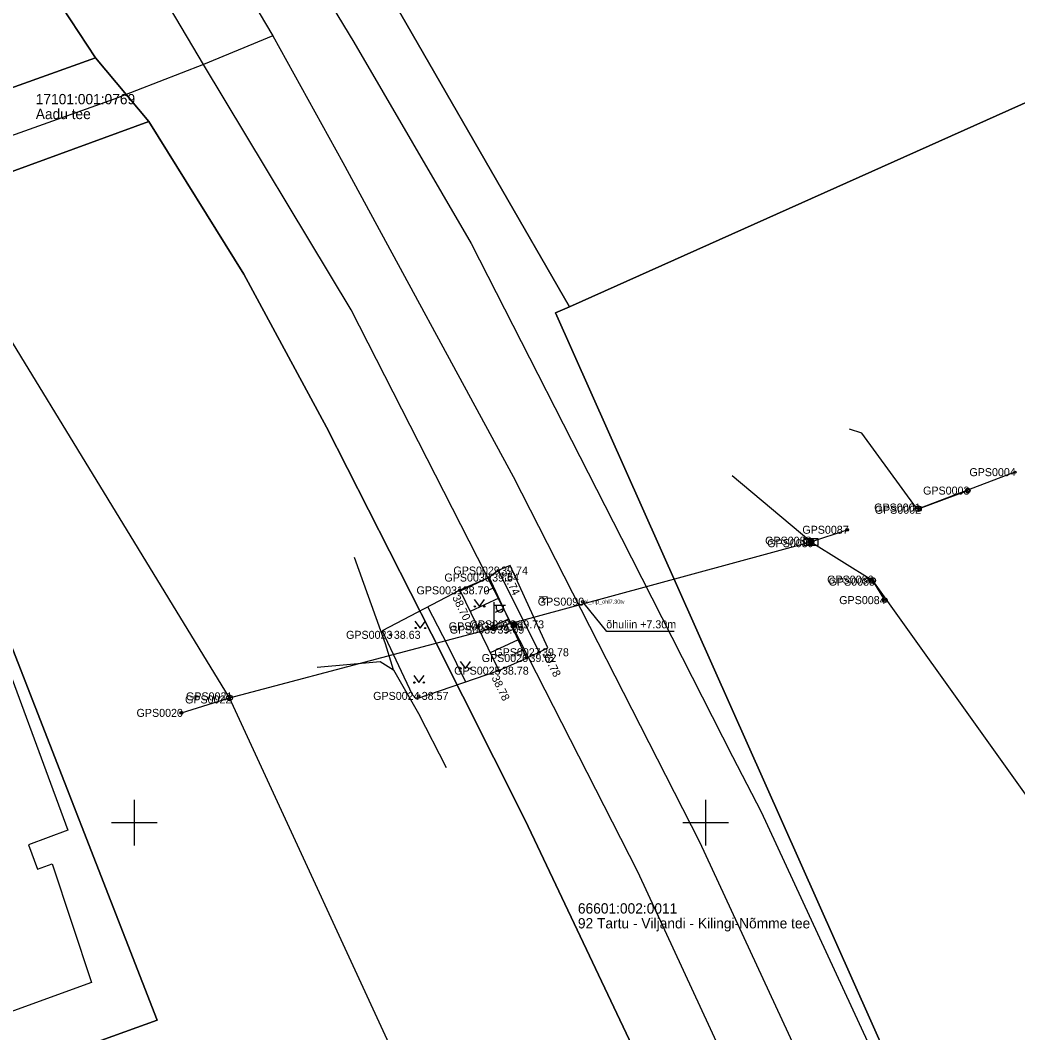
# Model space of a CAD drawing. Extents: x 626224 to 628280, y 6467750 to 6471135.
# Drawn here: x 627790 to 627877.3, y 6468381.6 to 6468470.2 of the extents above; entities that cross this region are included whole.
import ezdxf

# ---------------------------------------------------------------- set-up
doc = ezdxf.new("R2010")
doc.units = 0
for name, color, linetype in [('ELRAJATISMP', 7, 'Continuous'), ('HALJASTUS', 7, 'Continuous'), ('Hoone Elu- või ühiskondlik hoone', 7, 'Continuous'), ('KORGUS-EH2000', 7, 'Continuous'), ('KPKAABEL', 7, 'Continuous'), ('KPOHULIIN', 7, 'Continuous'), ('MAAMUDEL', 7, 'Continuous'), ('MOOTKORG-EH2000', 7, 'Continuous'), ('MOOTMPUNKT', 7, 'Continuous'), ('MOOTNR', 7, 'Continuous'), ('MOOTPIIR', 7, 'Continuous'), ('MPKAABEL', 7, 'Continuous'), ('MPOHULIIN', 7, 'Continuous'), ('PIIR', 7, 'Continuous'), ('POST', 7, 'Continuous'), ('RELJEEF', 7, 'Continuous'), ('SITRASS', 7, 'Continuous'), ('TEE', 7, 'Continuous'), ('Tee Liiklusala', 7, 'Continuous'), ('Tee Muu tee Püsikate', 7, 'Continuous'), ('Tee Põhimaantee Püsikate', 7, 'Continuous'), ('VORK', 7, 'Continuous')]:
    doc.layers.add(name, color=color, linetype=linetype)

msp = doc.modelspace()

# ---------------------------------------------------------------- linework, layer by layer
at = {"layer": 'ELRAJATISMP'}
for p, q in [((627859.089, 6468424.856), (627859.089, 6468424.259)), ((627859.36, 6468424.856), (627859.36, 6468424.259))]:
    msp.add_line(p, q, dxfattribs=at)
msp.add_lwpolyline([(627858.627, 6468424.856), (627859.822, 6468424.856), (627859.822, 6468424.259), (627858.627, 6468424.259)], close=True, dxfattribs=at)
at = {"layer": 'HALJASTUS'}
for p, q in [((627829.743, 6468419.52), (627830.207, 6468418.913)), ((627830.207, 6468418.913), (627830.652, 6468419.52)), ((627824.568, 6468417.633), (627825.031, 6468417.026)), ((627825.031, 6468417.026), (627825.477, 6468417.633)), ((627828.512, 6468414.09), (627828.975, 6468413.484)), ((627828.975, 6468413.484), (627829.421, 6468414.09)), ((627824.453, 6468412.858), (627824.916, 6468412.251)), ((627824.916, 6468412.251), (627825.362, 6468412.858))]:
    msp.add_line(p, q, dxfattribs=at)
for centre in [(627829.806, 6468418.913), (627830.634, 6468418.913), (627824.63, 6468417.026), (627825.459, 6468417.026), (627828.574, 6468413.484), (627829.403, 6468413.484), (627824.515, 6468412.251), (627825.344, 6468412.251)]:
    msp.add_circle(centre, 0.055, dxfattribs=at)
at = {"layer": 'Hoone Elu- või ühiskondlik hoone'}
msp.add_lwpolyline([(627782.134, 6468418.559), (627783.024, 6468416.148), (627787.374, 6468417.759), (627794.183, 6468399.339), (627790.744, 6468398.069), (627791.544, 6468395.918), (627792.806, 6468396.379), (627796.243, 6468386.017), (627788.121, 6468383.056), (627784.754, 6468393.178), (627785.402, 6468393.411), (627776.874, 6468416.554), (627776.074, 6468416.259), (627772.824, 6468425.129), (627780.904, 6468428.069), (627784.124, 6468419.309)], close=True, dxfattribs=at)
at = {"layer": 'KORGUS-EH2000'}
for centre in [(627831.853, 6468422.053), (627828.482, 6468420.323), (627822.455, 6468416.43), (627835.432, 6468414.905), (627831.919, 6468413.296), (627824.898, 6468411.085)]:
    msp.add_circle(centre, 0.1, dxfattribs=at)
at = {"layer": 'KPKAABEL'}
msp.add_lwpolyline([(627868.629, 6468427.468), (627868.453, 6468427.501), (627863.683, 6468434.084), (627862.597, 6468434.434)], dxfattribs=at)
at = {"layer": 'KPOHULIIN'}
msp.add_line((627877.08, 6468430.663), (627868.629, 6468427.468), dxfattribs=at)
at = {"layer": 'MOOTMPUNKT'}
for centre in [(627877.08, 6468430.663), (627872.956, 6468429.05), (627868.535, 6468427.565), (627868.723, 6468427.371), (627862.388, 6468425.622), (627859.134, 6468424.667), (627859.315, 6468424.448), (627831.853, 6468422.053), (627831.061, 6468421.44), (627864.562, 6468421.262), (627864.688, 6468421.082), (627828.482, 6468420.323), (627839.234, 6468419.334), (627865.687, 6468419.466), (627831.441, 6468417.175), (627833.263, 6468417.344), (627822.455, 6468416.43), (627831.527, 6468416.886), (627835.432, 6468414.905), (627834.326, 6468414.401), (627831.919, 6468413.296), (627808.306, 6468411.047), (627824.898, 6468411.085), (627808.362, 6468410.774), (627804.121, 6468409.6)]:
    msp.add_circle(centre, 0.1, dxfattribs=at)
at = {"layer": 'MOOTPIIR'}
msp.add_lwpolyline([(627824.32, 6468411.202), (627824.662, 6468410.817), (627831.919, 6468413.296), (627834.326, 6468414.401), (627835.432, 6468414.905), (627836.182, 6468415.277), (627832.898, 6468422.5), (627831.853, 6468422.053), (627831.061, 6468421.44), (627828.482, 6468420.323), (627821.691, 6468416.785)], close=True, dxfattribs=at)
at = {"layer": 'MPKAABEL'}
msp.add_line((627859.225, 6468424.557), (627852.332, 6468430.34), dxfattribs=at)
msp.add_lwpolyline([(627847.256, 6468416.733), (627841.35, 6468416.714), (627839.374, 6468419.171)], dxfattribs=at)
at = {"layer": 'MPOHULIIN'}
for points in [[(627835.693, 6468351.671), (627824.767, 6468375.343), (627808.334, 6468410.91), (627776.772, 6468462.547)], [(627834.957, 6468417.972), (627859.225, 6468424.557), (627864.625, 6468421.172)], [(627987.699, 6468154.836), (627974.224, 6468199.228), (627965.015, 6468229.514), (627942.938, 6468278.292), (627925.229, 6468317.293), (627901.803, 6468369.191), (627885.677, 6468391.746), (627864.625, 6468421.172)], [(627822.673, 6468414.701), (627831.484, 6468417.03), (627834.957, 6468417.972)], [(627808.334, 6468410.91), (627822.673, 6468414.701)]]:
    msp.add_lwpolyline(points, dxfattribs=at)
at = {"layer": 'PIIR'}
for points in [[(627932.6, 6468557.07), (627965.68, 6468502.25), (627838.09, 6468445.14), (627818.92, 6468478.42), (627816.33, 6468482.77), (627807.45, 6468497.75)], [(627796.62, 6468466.91), (627730.26, 6468443.18), (627664.7, 6468422.83), (627644.76, 6468421.52), (627633.52, 6468445.58), (627608.44, 6468499.25), (627666.94, 6468517.08), (627746.91, 6468541.23), (627793.54, 6468471.56), (627793.68, 6468471.35)], [(627965.68, 6468502.25), (628025.29, 6468403.44), (627924.44, 6468351.42), (627930.15, 6468335.32), (627893.5, 6468317.49), (627836.88, 6468444.6), (627838.09, 6468445.14)], [(627664.45, 6468365.98), (627644.76, 6468421.52), (627664.7, 6468422.83), (627730.26, 6468443.18), (627796.62, 6468466.91), (627801.28, 6468461.34), (627775.07, 6468451.79), (627729.69, 6468435.15), (627697.47, 6468426.57), (627658.9, 6468411.81), (627655.45, 6468401.9), (627668.1, 6468374.6), (627685.55, 6468339.27), (627702.17, 6468303.93), (627693.67, 6468299.87)], [(627802, 6468382.71), (627775.07, 6468451.79), (627801.28, 6468461.34), (627809.58, 6468448), (627816.81, 6468434.6), (627826.02, 6468416.53), (627834.21, 6468400.21), (627843.3, 6468381.02), (627850.92, 6468363.47), (627860.61, 6468341.12), (627869.05, 6468319.44), (627817.44, 6468300.95), (627762.12, 6468283.97), (627745.3, 6468323.41), (627778.35, 6468337.62), (627766.32, 6468369.86)], [(627775.07, 6468451.79), (627802, 6468382.71), (627766.32, 6468369.86), (627762.49, 6468377.13), (627743.21, 6468369.09), (627733.67, 6468392.46), (627728.72, 6468407.08), (627739.62, 6468413.09), (627729.69, 6468435.15)]]:
    msp.add_lwpolyline(points, close=True, dxfattribs=at)
msp.add_lwpolyline([(627869.05, 6468319.44), (627860.61, 6468341.12), (627850.92, 6468363.47), (627843.3, 6468381.02), (627834.21, 6468400.21), (627826.02, 6468416.53), (627816.81, 6468434.6), (627809.58, 6468448), (627801.28, 6468461.34), (627796.62, 6468466.91), (627793.68, 6468471.35), (627793.54, 6468471.56), (627816.33, 6468482.77), (627818.92, 6468478.42), (627838.09, 6468445.14), (627836.88, 6468444.6), (627893.5, 6468317.49)], dxfattribs=at)
at = {"layer": 'POST'}
for p, q in [((627831.484, 6468417.28), (627831.484, 6468419.28)), ((627831.484, 6468419.03), (627832.484, 6468419.03)), ((627831.711, 6468418.709), (627831.711, 6468419.03)), ((627832.324, 6468418.709), (627832.324, 6468419.03)), ((627833.085, 6468417.168), (627833.439, 6468417.521)), ((627831.484, 6468417.03), (627831.484, 6468417.03))]:
    msp.add_line(p, q, dxfattribs=at)
for points in [[(627868.629, 6468427.468), (627872.956, 6468429.05)], [(627859.225, 6468424.557), (627862.388, 6468425.622)], [(627865.687, 6468419.466), (627864.625, 6468421.172)], [(627804.121, 6468409.6), (627808.334, 6468410.91)]]:
    msp.add_lwpolyline(points, dxfattribs=at)
for centre, radius in [((627872.956, 6468429.05), 0.2), ((627868.629, 6468427.468), 0.25), ((627862.388, 6468425.622), 0.125), ((627862.388, 6468425.622), 0.105), ((627862.388, 6468425.622), 0.0851), ((627862.388, 6468425.622), 0.0651), ((627862.388, 6468425.622), 0.0451), ((627862.388, 6468425.622), 0.0251), ((627862.388, 6468425.622), 0.00511), ((627859.225, 6468424.557), 0.25), ((627864.625, 6468421.172), 0.25), ((627864.625, 6468421.172), 0.0234), ((627865.687, 6468419.466), 0.2), ((627831.484, 6468417.03), 0.25), ((627833.263, 6468417.344), 0.25), ((627808.334, 6468410.91), 0.25), ((627804.121, 6468409.6), 0.125), ((627804.121, 6468409.6), 0.105), ((627804.121, 6468409.6), 0.0851), ((627804.121, 6468409.6), 0.0651), ((627804.121, 6468409.6), 0.0451), ((627804.121, 6468409.6), 0.0251), ((627804.121, 6468409.6), 0.00511)]:
    msp.add_circle(centre, radius, dxfattribs=at)
for centre, radius, start, end in [((627832.017, 6468418.709), 0.306, 180, 0), ((627833.263, 6468417.344), 0.225, 224.85406, 45.03563), ((627833.263, 6468417.344), 0.2, 224.84272, 45.04698), ((627833.263, 6468417.344), 0.175, 224.82813, 45.06157), ((627833.263, 6468417.344), 0.15, 224.80867, 45.08103), ((627833.263, 6468417.344), 0.125, 224.78144, 45.10826), ((627833.263, 6468417.344), 0.1, 224.74058, 45.14911), ((627833.263, 6468417.344), 0.075, 224.67249, 45.2172), ((627833.263, 6468417.344), 0.05, 224.53632, 45.35338), ((627833.263, 6468417.344), 0.025, 224.12776, 45.76193)]:
    msp.add_arc(centre, radius, start, end, dxfattribs=at)
at = {"layer": 'RELJEEF'}
for p, q in [((627831.061, 6468421.44), (627828.514, 6468420.258)), ((627831.061, 6468421.44), (627834.326, 6468414.401)), ((627828.482, 6468420.323), (627831.919, 6468413.296)), ((627831.482, 6468420.533), (627830.723, 6468420.181)), ((627831.903, 6468419.626), (627829.392, 6468418.461)), ((627832.323, 6468418.719), (627831.576, 6468418.372)), ((627832.744, 6468417.812), (627830.271, 6468416.664)), ((627833.165, 6468416.904), (627832.429, 6468416.563)), ((627833.586, 6468415.997), (627831.15, 6468414.867)), ((627834.007, 6468415.09), (627833.282, 6468414.754))]:
    msp.add_line(p, q, dxfattribs=at)
at = {"layer": 'SITRASS'}
for points in [[(627822.696, 6468413.373), (627821.974, 6468415.639), (627819.276, 6468423.196)], [(627829.008, 6468412.301), (627827.445, 6468415.491), (627825.701, 6468418.874)], [(627816.008, 6468413.596), (627821.508, 6468414.106), (627822.696, 6468413.373), (627824.885, 6468409.551), (627827.286, 6468404.81)]]:
    msp.add_lwpolyline(points, dxfattribs=at)
at = {"layer": 'TEE'}
msp.add_line((627831.853, 6468422.053), (627835.432, 6468414.905), dxfattribs=at)
at = {"layer": 'Tee Liiklusala'}
for points in [[(628004.712, 6467966.979), (627997.81, 6467987.98), (627990.136, 6468009.252), (627982.428, 6468031.57), (627970.386, 6468066.341), (627943.56, 6468142.05), (627938.773, 6468155.662), (627916.353, 6468218.793), (627896.06, 6468271.56), (627889.692, 6468286.926), (627880.369, 6468309.48), (627875.602, 6468321.934), (627863.15, 6468354.49), (627844.06, 6468395.68), (627818.98, 6468444.86), (627806.067, 6468466.343), (627794.52, 6468485.83), (627778.37, 6468512.41), (627770.48, 6468525.39), (627740.557, 6468568.764)], [(627760.92, 6468560.36), (627780.56, 6468531.91), (627795.194, 6468507.826), (627804.8, 6468492.03), (627819.213, 6468468.282), (627829.48, 6468450.66), (627842.629, 6468424.884), (627852.37, 6468405.79), (627854.86, 6468400.94), (627874.21, 6468359.17), (627891.81, 6468313.11), (627897.891, 6468298.46), (627907.18, 6468276.08), (627914.223, 6468258.331), (627924.31, 6468232.91), (627926.05, 6468227.94), (627930.17, 6468216.22), (627939.76, 6468188.97), (627954.88, 6468146.07), (627973.905, 6468092.359), (627984.638, 6468061.117)]]:
    msp.add_lwpolyline(points, dxfattribs=at)
at = {"layer": 'Tee Muu tee Püsikate'}
msp.add_lwpolyline([(627812.119, 6468468.847), (627806.067, 6468466.343), (627798.242, 6468463.296), (627758.885, 6468449.271)], dxfattribs=at)
at = {"layer": 'Tee Põhimaantee Püsikate'}
for points in [[(627700.902, 6468634.138), (627743.449, 6468575.098), (627775.098, 6468528.301), (627799.448, 6468490.206), (627812.119, 6468468.847)], [(627812.119, 6468468.847), (627818.257, 6468457.757), (627833.152, 6468430.273), (627849.46, 6468398.31), (627868.68, 6468356.83), (627882.943, 6468321.192), (627886.597, 6468311.791)]]:
    msp.add_lwpolyline(points, dxfattribs=at)
at = {"layer": 'VORK'}
for p, q in [((627800, 6468402), (627800, 6468398)), ((627850, 6468402), (627850, 6468398)), ((627798, 6468400), (627802, 6468400)), ((627848, 6468400), (627852, 6468400))]:
    msp.add_line(p, q, dxfattribs=at)

# ---------------------------------------------------------------- texts
at = {"layer": 'KORGUS-EH2000'}
for s, rotation, p in [(' 39.74', 296.59454, (627832.01, 6468422.132)), (' 38.70', 296.05959, (627827.696, 6468419.938)), (' 39.78', 296.59454, (627835.589, 6468414.984)), (' 38.78', 296.05959, (627831.132, 6468412.911))]:
    msp.add_text(s, height=0.7, rotation=rotation, dxfattribs=at).set_placement(p)
for s, p in [(' 38.63', (627822.455, 6468416.08)), (' 38.57', (627824.898, 6468410.735))]:
    msp.add_text(s, height=0.7, dxfattribs=at).set_placement(p)
at = {"layer": 'MAAMUDEL'}
msp.add_text(' el_mp_ohl7.30tv', height=0.35, dxfattribs=at).set_placement((627839.234, 6468419.159))
at = {"layer": 'MOOTKORG-EH2000'}
for s, p in [(' 39.64', (627831.061, 6468421.09)), (' 39.74', (627831.853, 6468421.703)), (' 38.70', (627828.482, 6468419.973)), (' 39.09', (627831.441, 6468416.825)), (' 39.09', (627831.527, 6468416.536)), (' 39.73', (627833.263, 6468416.994)), (' 38.63', (627822.455, 6468416.08)), (' 39.62', (627834.326, 6468414.051)), (' 39.78', (627835.432, 6468414.555)), (' 38.78', (627831.919, 6468412.946)), (' 38.57', (627824.898, 6468410.735))]:
    msp.add_text(s, height=0.7, dxfattribs=at).set_placement(p)
at = {"layer": 'MOOTNR'}
for s, p in [('GPS0004 ', (627873.09, 6468430.313)), ('GPS0003 ', (627869.036, 6468428.7)), ('GPS0001 ', (627864.755, 6468427.215)), ('GPS0002 ', (627864.804, 6468427.021)), ('GPS0087 ', (627858.469, 6468425.272)), ('GPS0088 ', (627855.214, 6468424.317)), ('GPS0089 ', (627855.396, 6468424.098)), ('GPS0030 ', (627827.141, 6468421.09)), ('GPS0029 ', (627827.934, 6468421.703)), ('GPS0086 ', (627860.642, 6468420.911)), ('GPS0085 ', (627860.768, 6468420.732)), ('GPS0031 ', (627824.702, 6468419.973)), ('GPS0090 ', (627835.314, 6468418.984)), ('GPS0084 ', (627861.697, 6468419.116)), ('GPS0032 ', (627827.521, 6468416.825)), ('GPS0033 ', (627827.607, 6468416.536)), ('GPS0028 ', (627829.343, 6468416.994)), ('GPS0023 ', (627818.535, 6468416.08)), ('GPS0026 ', (627830.407, 6468414.051)), ('GPS0027 ', (627831.512, 6468414.555)), ('GPS0025 ', (627827.999, 6468412.946)), ('GPS0022 ', (627804.442, 6468410.424)), ('GPS0021 ', (627804.527, 6468410.697)), ('GPS0024 ', (627820.908, 6468410.735)), ('GPS0020 ', (627800.201, 6468409.25))]:
    msp.add_text(s, height=0.7, dxfattribs=at).set_placement(p)
at = {"layer": 'MPKAABEL'}
msp.add_text('õhuliin +7.30m', height=0.7, dxfattribs=at).set_placement((627841.311, 6468416.999))
at = {"layer": 'PIIR'}
for s, p in [('17101:001:0769', (627791.378, 6468462.853)), ('Aadu tee', (627791.378, 6468461.553)), ('66601:002:0011', (627838.826, 6468392.042)), ('92 Tartu - Viljandi - Kilingi-Nõmme tee', (627838.826, 6468390.742))]:
    msp.add_text(s, height=0.9, dxfattribs=at).set_placement(p)
at = {"layer": 'TEE'}
msp.add_text('A', height=0.7, rotation=292.00814, dxfattribs=at).set_placement((627835.412, 6468419.793))
msp.add_text('A', height=0.7, rotation=292.00814, dxfattribs=at).set_placement((627835.412, 6468419.793))

doc.saveas('drawing.dxf')
